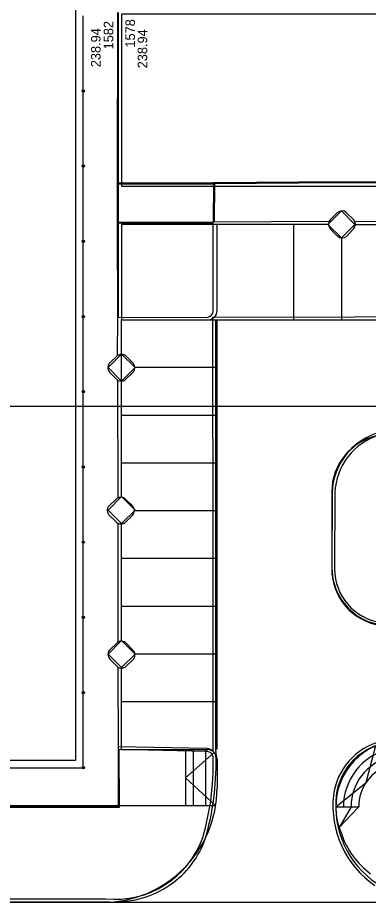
# Model space of a CAD drawing. Extents: x -264205 to -263659, y -1242401 to -1241986.
# Drawn here: x -263975.5 to -263957.16, y -1242301.53 to -1242255.16 of the extents above; entities that cross this region are included whole.
import ezdxf

# ---------------------------------------------------------------- set-up
doc = ezdxf.new("R2010")
doc.units = 0
for name, color, linetype in [('BOD_CISLO_2-3', 7, 'Continuous'), ('BOD_VYSKA_2-3', 7, 'Continuous'), ('PROJEKT_OBRUBNIKY_KOMUNIKACIE', 7, 'Continuous'), ('PROJEKT_TDZ_VODOROVNE', 7, 'Continuous'), ('RAM_NA_TLAC_2-3_1-250', 7, 'Continuous'), ('SITUACIA_DSP_2D', 7, 'Continuous'), ('SO_20-1_OBRUBNIKY_DOLNA_HRANA', 7, 'Continuous'), ('SO_20-1_OBRUBNIKY_HORNA_HRANA', 7, 'Continuous'), ('SO_20-2_OBRUBNIKY_DOLNA_HRANA', 7, 'Continuous'), ('SO_20-2_OBRUBNIKY_HORNA_HRANA', 7, 'Continuous')]:
    doc.layers.add(name, color=color, linetype=linetype)

msp = doc.modelspace()

# ---------------------------------------------------------------- linework, layer by layer
at = {"layer": 'PROJEKT_OBRUBNIKY_KOMUNIKACIE'}
for p, q in [((-263959.275, -1242265.982), (-263970.068, -1242265.982)), ((-263965.068, -1242270.482), (-263965.068, -1242265.982)), ((-263957.861, -1242265.982), (-263951.031, -1242265.982)), ((-263970.065, -1242280.238), (-263970.068, -1242270.982)), ((-263965.568, -1242270.982), (-263929.061, -1242270.982)), ((-263965.068, -1242293.482), (-263965.068, -1242270.982)), ((-263956.668, -1242277.043), (-263957.228, -1242277.216)), ((-263957.743, -1242277.494), (-263958.195, -1242277.867)), ((-263957.228, -1242277.216), (-263957.743, -1242277.494)), ((-263958.195, -1242277.867), (-263958.566, -1242278.321)), ((-263958.566, -1242278.321), (-263958.841, -1242278.838)), ((-263958.841, -1242278.838), (-263959.011, -1242279.399)), ((-263959.011, -1242279.399), (-263959.068, -1242279.982)), ((-263959.068, -1242279.982), (-263959.068, -1242283.982)), ((-263970.068, -1242287.775), (-263970.068, -1242281.649)), ((-263959.068, -1242283.982), (-263959.011, -1242284.565)), ((-263959.011, -1242284.565), (-263958.841, -1242285.126)), ((-263958.841, -1242285.126), (-263958.566, -1242285.644)), ((-263958.566, -1242285.644), (-263958.195, -1242286.098)), ((-263958.195, -1242286.098), (-263957.743, -1242286.471)), ((-263957.743, -1242286.471), (-263957.228, -1242286.749)), ((-263957.228, -1242286.749), (-263956.668, -1242286.922)), ((-263970.068, -1242293.482), (-263970.068, -1242289.189)), ((-263970.068, -1242293.482), (-263965.568, -1242293.482)), ((-263966.714, -1242293.482), (-263966.714, -1242296.432)), ((-263965.068, -1242293.982), (-263965.068, -1242295.482)), ((-263971.068, -1242301.482), (-264112.961, -1242301.482))]:
    msp.add_line(p, q, dxfattribs=at)
for points in [[(-264042.568, -1242294.032), (-263972.468, -1242294.032), (-263972.468, -1242187.932), (-264042.568, -1242187.932), (-264042.568, -1242294.032)], [(-263929.58, -1242254.982), (-263970.077, -1242254.982), (-263970.077, -1242263.982), (-263929.58, -1242263.982), (-263929.58, -1242254.982)], [(-263958.568, -1242265.275), (-263957.861, -1242265.982), (-263958.568, -1242266.689), (-263959.275, -1242265.982), (-263958.568, -1242265.275)], [(-263970.068, -1242265.982), (-263970.068, -1242270.982), (-263965.568, -1242270.982)], [(-263970.068, -1242272.775), (-263969.361, -1242273.482), (-263970.068, -1242274.189), (-263970.775, -1242273.482), (-263970.068, -1242272.775)], [(-263970.068, -1242280.235), (-263969.361, -1242280.942), (-263970.068, -1242281.649), (-263970.775, -1242280.942), (-263970.068, -1242280.235)], [(-263970.068, -1242287.775), (-263969.361, -1242288.482), (-263970.068, -1242289.189), (-263970.775, -1242288.482), (-263970.068, -1242287.775)], [(-263958.859, -1242296.482), (-263957.268, -1242295.199), (-263956.756, -1242293.273)], [(-263965.214, -1242293.629), (-263966.714, -1242294.957), (-263965.143, -1242296.432)], [(-263965.143, -1242296.432), (-264120.018, -1242296.432), (-264120.282, -1242296.432)], [(-263958.859, -1242296.482), (-263957.659, -1242296.482), (-263958.688, -1242297.562)]]:
    msp.add_lwpolyline(points, dxfattribs=at)
for centre, radius, start, end in [((-263965.568, -1242270.482), 0.5, 270, 0), ((-263955.359, -1242296.482), 3.5, 113.7599, 203.5782), ((-263965.568, -1242293.982), 0.5, 0, 90), ((-263955.359, -1242296.482), 2.3, 107.9469, 180), ((-263971.068, -1242295.482), 6, 270, 0), ((-263954.444, -1242296.485), 4.353, 198.7173, 233.4513)]:
    msp.add_arc(centre, radius, start, end, dxfattribs=at)
at = {"layer": 'PROJEKT_TDZ_VODOROVNE'}
for p, q in [((-263961.068, -1242265.982), (-263961.068, -1242270.982)), ((-263958.568, -1242266.689), (-263958.568, -1242270.982)), ((-263965.068, -1242273.482), (-263969.361, -1242273.482)), ((-263965.068, -1242275.982), (-263970.068, -1242275.982)), ((-263965.068, -1242278.482), (-263970.068, -1242278.482)), ((-263965.068, -1242280.982), (-263969.401, -1242280.982)), ((-263965.068, -1242283.482), (-263970.068, -1242283.482)), ((-263965.068, -1242285.982), (-263970.068, -1242285.982)), ((-263965.068, -1242288.482), (-263969.361, -1242288.482)), ((-263965.068, -1242290.982), (-263970.068, -1242290.982)), ((-263953.068, -1242301.482), (-263971.068, -1242301.482))]:
    msp.add_line(p, q, dxfattribs=at)
at = {"layer": 'RAM_NA_TLAC_2-3_1-250'}
msp.add_lwpolyline([(-263980.139, -1242275.511), (-263980.139, -1241985.511), (-263905.889, -1241985.511), (-263905.889, -1242275.511)], close=True, dxfattribs=at)
at = {"layer": 'SITUACIA_DSP_2D'}
for p, q in [((-263972.468, -1242294.032), (-263972.468, -1242187.932)), ((-263972.068, -1242294.432), (-263972.068, -1242255.057)), ((-263970.077, -1242254.982), (-263970.077, -1242263.982)), ((-263972.128, -1242258.995), (-263972.008, -1242258.995)), ((-263972.068, -1242259.055), (-263972.068, -1242258.935)), ((-263972.128, -1242262.932), (-263972.008, -1242262.932)), ((-263972.068, -1242262.992), (-263972.068, -1242262.872)), ((-263970.077, -1242263.982), (-263929.58, -1242263.982)), ((-263959.275, -1242265.982), (-263958.568, -1242265.275)), ((-263958.568, -1242265.275), (-263957.861, -1242265.982)), ((-263965.068, -1242265.982), (-263970.068, -1242265.982)), ((-263965.068, -1242270.482), (-263965.068, -1242265.982)), ((-263958.568, -1242266.689), (-263959.275, -1242265.982)), ((-263957.861, -1242265.982), (-263958.568, -1242266.689)), ((-263972.128, -1242266.87), (-263972.008, -1242266.87)), ((-263972.068, -1242266.93), (-263972.068, -1242266.81)), ((-263972.128, -1242270.807), (-263972.008, -1242270.807)), ((-263972.068, -1242270.867), (-263972.068, -1242270.747)), ((-263970.065, -1242280.238), (-263970.068, -1242270.982)), ((-263970.775, -1242273.482), (-263970.068, -1242272.775)), ((-263970.068, -1242272.775), (-263969.361, -1242273.482)), ((-263970.068, -1242274.189), (-263970.775, -1242273.482)), ((-263969.361, -1242273.482), (-263970.068, -1242274.189)), ((-263972.128, -1242274.745), (-263972.008, -1242274.745)), ((-263972.068, -1242274.805), (-263972.068, -1242274.685)), ((-263972.128, -1242278.682), (-263972.008, -1242278.682)), ((-263972.068, -1242278.742), (-263972.068, -1242278.622)), ((-263970.775, -1242280.942), (-263970.068, -1242280.235)), ((-263970.068, -1242280.235), (-263969.361, -1242280.942)), ((-263959.068, -1242279.982), (-263959.068, -1242283.982)), ((-263970.068, -1242281.649), (-263970.775, -1242280.942)), ((-263969.361, -1242280.942), (-263970.068, -1242281.649)), ((-263970.068, -1242287.775), (-263970.068, -1242281.649)), ((-263972.128, -1242282.62), (-263972.008, -1242282.62)), ((-263972.068, -1242282.68), (-263972.068, -1242282.56)), ((-263972.128, -1242286.557), (-263972.008, -1242286.557)), ((-263972.068, -1242286.617), (-263972.068, -1242286.497)), ((-263970.775, -1242288.482), (-263970.068, -1242287.775)), ((-263970.068, -1242287.775), (-263969.361, -1242288.482)), ((-263970.068, -1242289.189), (-263970.775, -1242288.482)), ((-263969.361, -1242288.482), (-263970.068, -1242289.189)), ((-263970.068, -1242293.482), (-263970.068, -1242289.189)), ((-263972.128, -1242290.495), (-263972.008, -1242290.495)), ((-263972.068, -1242290.555), (-263972.068, -1242290.435)), ((-263970.068, -1242293.482), (-263965.568, -1242293.482)), ((-263966.314, -1242293.482), (-263966.314, -1242296.432)), ((-263965.684, -1242293.482), (-263965.684, -1242296.432)), ((-264042.568, -1242294.032), (-263972.468, -1242294.032)), ((-263965.068, -1242293.982), (-263965.068, -1242295.482)), ((-264045.118, -1242294.432), (-263972.068, -1242294.432)), ((-263972.128, -1242294.432), (-263972.008, -1242294.432)), ((-263972.068, -1242294.492), (-263972.068, -1242294.372)), ((-263965.143, -1242296.432), (-264120.018, -1242296.432)), ((-263958.859, -1242296.482), (-263958.059, -1242296.482)), ((-263958.059, -1242296.482), (-263958.688, -1242297.562)), ((-263971.068, -1242301.482), (-264112.961, -1242301.482))]:
    msp.add_line(p, q, dxfattribs=at)
msp.add_lwpolyline([(-263970.068, -1242265.982), (-263970.068, -1242270.982), (-263965.568, -1242270.982)], dxfattribs=at)
for centre in [(-263972.068, -1242258.995), (-263972.068, -1242262.932), (-263972.068, -1242266.87), (-263972.068, -1242270.807), (-263972.068, -1242274.745), (-263972.068, -1242278.682), (-263972.068, -1242282.62), (-263972.068, -1242286.557), (-263972.068, -1242290.495), (-263972.068, -1242294.432)]:
    msp.add_circle(centre, 0.06, dxfattribs=at)
for centre, radius, start, end in [((-263965.568, -1242270.482), 0.5, 270, 0), ((-263956.068, -1242279.982), 3, 101.537, 180), ((-263956.068, -1242283.982), 3, 180, 258.463), ((-263955.359, -1242296.482), 3.5, 113.7599, 203.5782), ((-263965.568, -1242293.982), 0.5, 0, 90), ((-263955.359, -1242296.482), 3.1, 104.5457, 180), ((-263955.359, -1242296.482), 2.7, 105.2176, 180), ((-263971.068, -1242295.482), 6, 270, 0), ((-263954.444, -1242296.485), 4.353, 198.7173, 233.4513)]:
    msp.add_arc(centre, radius, start, end, dxfattribs=at)
at = {"layer": 'SO_20-1_OBRUBNIKY_DOLNA_HRANA'}
msp.add_lwpolyline([(-263993.952, -1242301.425), (-263986.921, -1242301.437), (-263979.924, -1242301.441), (-263972.919, -1242301.445), (-263970.912, -1242301.438)], dxfattribs=at)
at = {"layer": 'SO_20-1_OBRUBNIKY_HORNA_HRANA'}
msp.add_lwpolyline([(-263993.949, -1242301.276), (-263986.923, -1242301.287), (-263979.923, -1242301.293), (-263972.92, -1242301.295), (-263970.913, -1242301.29)], dxfattribs=at)
at = {"layer": 'SO_20-2_OBRUBNIKY_DOLNA_HRANA'}
for p, q in [((-263959.054, -1242280.029), (-263959.07, -1242284.016)), ((-263965.599, -1242293.429), (-263970.229, -1242293.332)), ((-263965.127, -1242293.556), (-263965.124, -1242293.935))]:
    msp.add_line(p, q, dxfattribs=at)
for points in [[(-263965.289, -1242270.846), (-263957.9, -1242270.825), (-263950.806, -1242270.811), (-263943.808, -1242270.801), (-263936.795, -1242270.772), (-263929.578, -1242270.752)], [(-263965.273, -1242293.566), (-263965.279, -1242283.55), (-263965.289, -1242270.846)], [(-263965.143, -1242270.987), (-263957.899, -1242270.977), (-263950.804, -1242270.956), (-263943.803, -1242270.944), (-263936.794, -1242270.917), (-263929.31, -1242270.895)], [(-263965.127, -1242293.556), (-263965.137, -1242283.552), (-263965.143, -1242270.987)]]:
    msp.add_lwpolyline(points, dxfattribs=at)
for centre, major_axis, ratio, start_param, end_param in [((-263955.655, -1242280.15), (-0.469, 3.371), 0.999366, 0.126889, 1.396912), ((-263956.094, -1242284.026), (2.785, -1.049), 0.999986, 3.498387, 4.942262), ((-263955.768, -1242296.156), (-2.482, -2.14), 0.96746, 4.242283, 5.470279), ((-263965.612, -1242293.917), (0.451, -0.189), 0.998943, 0.361501, 1.941121), ((-263975.124, -1242294.767), (1.6, 11.839), 0.833992, 4.538826, 4.894527), ((-263953.969, -1242296.438), (-5.036, -0.207), 0.999986, 6.131722, 7.212659), ((-263970.302, -1242296.531), (2.317, 4.313), 0.999794, 4.231365, 4.873428), ((-263970.409, -1242296.372), (3.223, 3.948), 0.997928, 4.115934, 4.423221), ((-263970.424, -1242296.405), (5.06, -0.539), 0.993811, 4.721762, 5.109666)]:
    msp.add_ellipse(centre, major_axis=major_axis, ratio=ratio, start_param=start_param, end_param=end_param, dxfattribs=at)
at = {"layer": 'SO_20-2_OBRUBNIKY_HORNA_HRANA'}
for p, q in [((-263970.227, -1242263.807), (-263965.254, -1242263.802)), ((-263970.227, -1242263.854), (-263965.255, -1242263.85)), ((-263970.227, -1242265.862), (-263965.276, -1242265.854)), ((-263970.227, -1242265.907), (-263965.276, -1242265.898)), ((-263965.276, -1242265.854), (-263959.204, -1242265.822)), ((-263965.275, -1242270.488), (-263965.276, -1242265.854)), ((-263957.867, -1242265.823), (-263950.988, -1242265.812)), ((-263959.134, -1242266.23), (-263958.778, -1242266.585)), ((-263970.666, -1242273.218), (-263970.318, -1242272.887)), ((-263969.813, -1242272.892), (-263969.467, -1242273.254)), ((-263970.692, -1242273.721), (-263970.353, -1242274.076)), ((-263969.488, -1242273.752), (-263969.847, -1242274.091)), ((-263970.249, -1242280.3), (-263970.267, -1242274.144)), ((-263970.722, -1242280.716), (-263970.369, -1242280.384)), ((-263969.856, -1242280.377), (-263969.502, -1242280.716)), ((-263958.906, -1242280.03), (-263958.926, -1242284.016)), ((-263970.355, -1242281.565), (-263970.705, -1242281.224)), ((-263969.497, -1242281.223), (-263969.847, -1242281.563)), ((-263970.239, -1242287.847), (-263970.248, -1242281.638)), ((-263970.671, -1242288.237), (-263970.314, -1242287.901)), ((-263969.807, -1242287.92), (-263969.472, -1242288.273)), ((-263970.335, -1242289.101), (-263970.675, -1242288.742)), ((-263969.482, -1242288.784), (-263969.826, -1242289.114))]:
    msp.add_line(p, q, dxfattribs=at)
for points in [[(-263970.27, -1242270.832), (-263970.272, -1242265.906), (-263970.272, -1242263.853), (-263970.27, -1242254.881)], [(-263970.227, -1242270.832), (-263970.227, -1242265.907), (-263970.227, -1242263.854), (-263970.225, -1242254.882)], [(-263927.032, -1242263.694), (-263929.858, -1242263.715), (-263931.859, -1242263.708), (-263939.843, -1242263.726), (-263948.832, -1242263.749), (-263954.816, -1242263.759), (-263960.791, -1242263.777), (-263965.254, -1242263.802), (-263965.276, -1242265.854)], [(-263927.18, -1242263.745), (-263929.889, -1242263.765), (-263931.859, -1242263.758), (-263939.843, -1242263.776), (-263948.832, -1242263.799), (-263954.816, -1242263.809), (-263960.791, -1242263.827), (-263965.205, -1242263.852), (-263965.226, -1242265.854)], [(-263958.785, -1242265.376), (-263959.146, -1242265.738)], [(-263957.936, -1242265.727), (-263958.291, -1242265.374)], [(-263958.287, -1242266.595), (-263957.928, -1242266.222)], [(-263970.276, -1242272.851), (-263970.27, -1242270.832), (-263965.636, -1242270.85)], [(-263965.616, -1242293.582), (-263970.229, -1242293.474), (-263970.237, -1242289.176)], [(-264048.312, -1242296.489), (-264028.434, -1242296.487), (-264007.811, -1242296.484), (-263989.348, -1242296.492), (-263970.175, -1242296.491), (-263970.185, -1242293.475)], [(-264048.263, -1242296.44), (-264028.48, -1242296.445), (-264007.857, -1242296.442), (-263989.394, -1242296.45), (-263970.221, -1242296.449), (-263970.229, -1242293.474)]]:
    msp.add_lwpolyline(points, dxfattribs=at)
for centre, major_axis, ratio, start_param, end_param in [((-263958.537, -1242265.623), (-0.323, 0.135), 0.999783, 4.328397, 5.895389), ((-263958.886, -1242265.978), (-0.181, -0.304), 0.999535, 4.506104, 6.043127), ((-263958.187, -1242265.979), (-0.251, 0.252), 0.999847, 3.1764, 4.716307), ((-263958.527, -1242266.332), (0.22, -0.28), 0.999969, 4.836879, 6.356561), ((-263965.627, -1242270.498), (0.328, 0.126), 0.999435, 4.318529, 5.945352), ((-263970.068, -1242273.142), (-0.343, 0.098), 0.999556, 4.196305, 5.766372), ((-263970.439, -1242273.482), (-0.048, -0.345), 0.999733, 3.988836, 5.608141), ((-263969.725, -1242273.493), (0.001, -0.352), 0.999056, 0.736918, 2.312272), ((-263970.093, -1242273.839), (0.352, -0.01), 0.999301, 3.910899, 5.513879), ((-263955.636, -1242280.153), (0.058, 3.275), 0.999165, 0.301718, 1.55091), ((-263970.109, -1242280.629), (-0.352, 0.061), 0.99949, 4.094713, 5.698395), ((-263970.467, -1242280.962), (0.236, -0.264), 0.999925, 3.215899, 4.816729), ((-263969.757, -1242280.972), (0.062, 0.356), 0.999459, 4.116697, 5.669865), ((-263970.102, -1242281.31), (-0.343, -0.109), 0.999217, 0.483156, 2.052302), ((-263956.072, -1242284.009), (-2.548, 1.287), 0.999996, 0.470217, 1.888537), ((-263970.07, -1242288.159), (-0.355, 0.013), 0.999288, 3.917935, 5.506843), ((-263970.424, -1242288.491), (0.003, 0.355), 0.999593, 0.778416, 2.363176), ((-263969.724, -1242288.524), (0.149, 0.323), 0.999988, 4.324643, 5.928423), ((-263970.074, -1242288.863), (-0.351, -0.041), 0.999905, 0.622142, 2.233058), ((-263955.804, -1242296.126), (-2.333, -2.037), 0.964506, 4.227389, 5.472895), ((-263965.619, -1242293.93), (0.033, 0.347), 0.999874, 4.786425, 6.369423), ((-263974.901, -1242294.791), (1.539, 11.392), 0.83473, 4.533478, 4.89912), ((-263954.001, -1242296.449), (-4.851, -0.368), 0.999992, 6.094406, 7.182473), ((-263970.392, -1242296.461), (-2.525, -4.15), 0.999251, 0.439488, 1.776776)]:
    msp.add_ellipse(centre, major_axis=major_axis, ratio=ratio, start_param=start_param, end_param=end_param, dxfattribs=at)

# ---------------------------------------------------------------- texts
at = {"layer": 'BOD_CISLO_2-3'}
for s, p in [('1578', (-263969.367, -1242256.724)), ('1582', (-263970.501, -1242256.819))]:
    msp.add_text(s, height=0.5, rotation=90, dxfattribs=at).set_placement(p)
at = {"layer": 'BOD_VYSKA_2-3'}
for p in [(-263971.166, -1242257.753), (-263968.724, -1242257.81)]:
    msp.add_text('238.94', height=0.5, rotation=90, dxfattribs=at).set_placement(p)

doc.saveas('drawing.dxf')
